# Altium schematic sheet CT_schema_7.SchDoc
size 277 x 170 mm
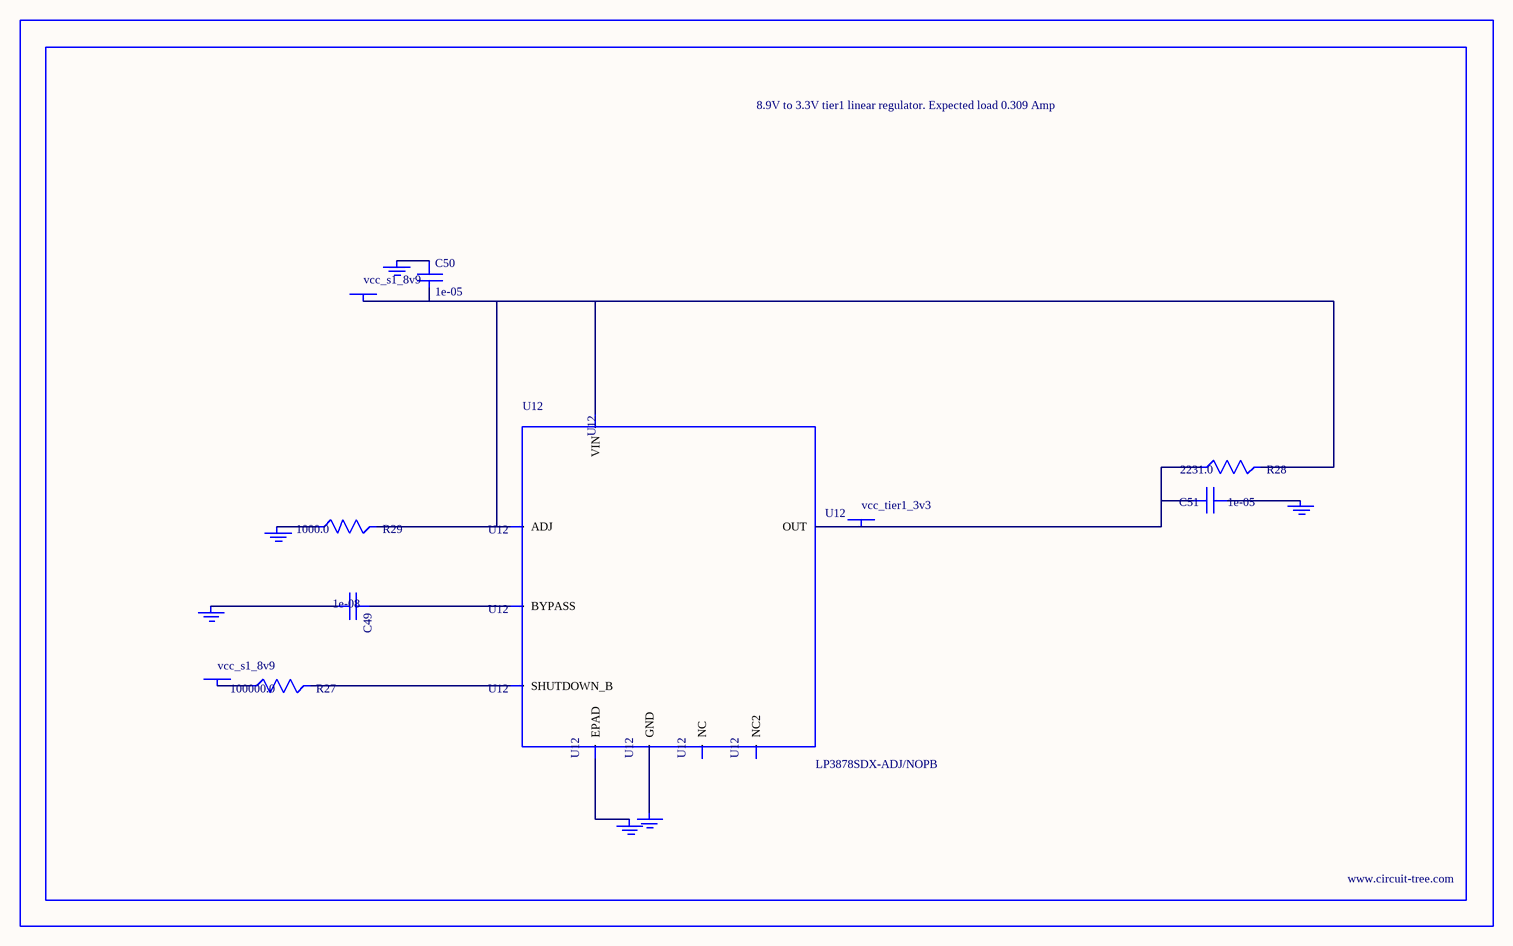
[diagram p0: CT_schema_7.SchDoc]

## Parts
BORDER6  (no value)
C49  1e-08  [C0402]
C50  1e-05  [C1206]
C51  1e-05  [C1210]
GND_INSTANCE_6_0  (no value)
GND_INSTANCE_6_1  (no value)
GND_INSTANCE_6_2  (no value)
GND_INSTANCE_6_3  (no value)
GND_INSTANCE_6_4  (no value)
GND_INSTANCE_6_5  (no value)
POWER_INSTANCE_6_0  vcc_s1_8v9
POWER_INSTANCE_6_1  vcc_s1_8v9
POWER_INSTANCE_6_2  vcc_tier1_3v3
R27  100000.0  [R0603]
R28  2231.0  [R0603]
R29  1000.0  [R0603]
U12  LP3878SDX-ADJ/NOPB  [WSON-8]

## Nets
NetC49_1: C49.1 U12.1(BYPASS)
NetC49_2: C49.2 GND_INSTANCE_6_0.0(GND)
NetC50_1: C50.1 GND_INSTANCE_6_1.0(GND)
NetC50_2: C50.2 POWER_INSTANCE_6_0.0(PWR) R28.2 R29.2 U12.4(VIN) U12.6(ADJ)
NetC51_1: C51.1 GND_INSTANCE_6_2.0(GND)
NetC51_2: C51.2 POWER_INSTANCE_6_2.0(PWR) R28.1 U12.5(OUT)
NetGND_INSTANCE_6_3_0: GND_INSTANCE_6_3.0(GND) R29.1
NetGND_INSTANCE_6_4_0: GND_INSTANCE_6_4.0(GND) U12.PAD(EPAD)
NetGND_INSTANCE_6_5_0: GND_INSTANCE_6_5.0(GND) U12.3(GND)
NetPOWER_INSTANCE_6_1_0: POWER_INSTANCE_6_1.0(PWR) R27.1
NetR27_2: R27.2 U12.8(SHUTDOWN_B)

Not connected (* = marked no-connect by the designer): U12 2(NC) 7(NC2)

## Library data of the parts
BORDER6 = BORDER_PAGE6
C49 = C0402C103K3RAC
C50 = C1206C106K3RACTU
C51 = GRM32DR61E106MA12L
GND_INSTANCE_6_0-GND_INSTANCE_6_5 = GND
POWER_INSTANCE_6_0-POWER_INSTANCE_6_2 = PWR
R27 = RC0603JR-07100KL
R28 = R28
R29 = RC0603JR-071KL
